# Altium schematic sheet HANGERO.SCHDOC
size A2
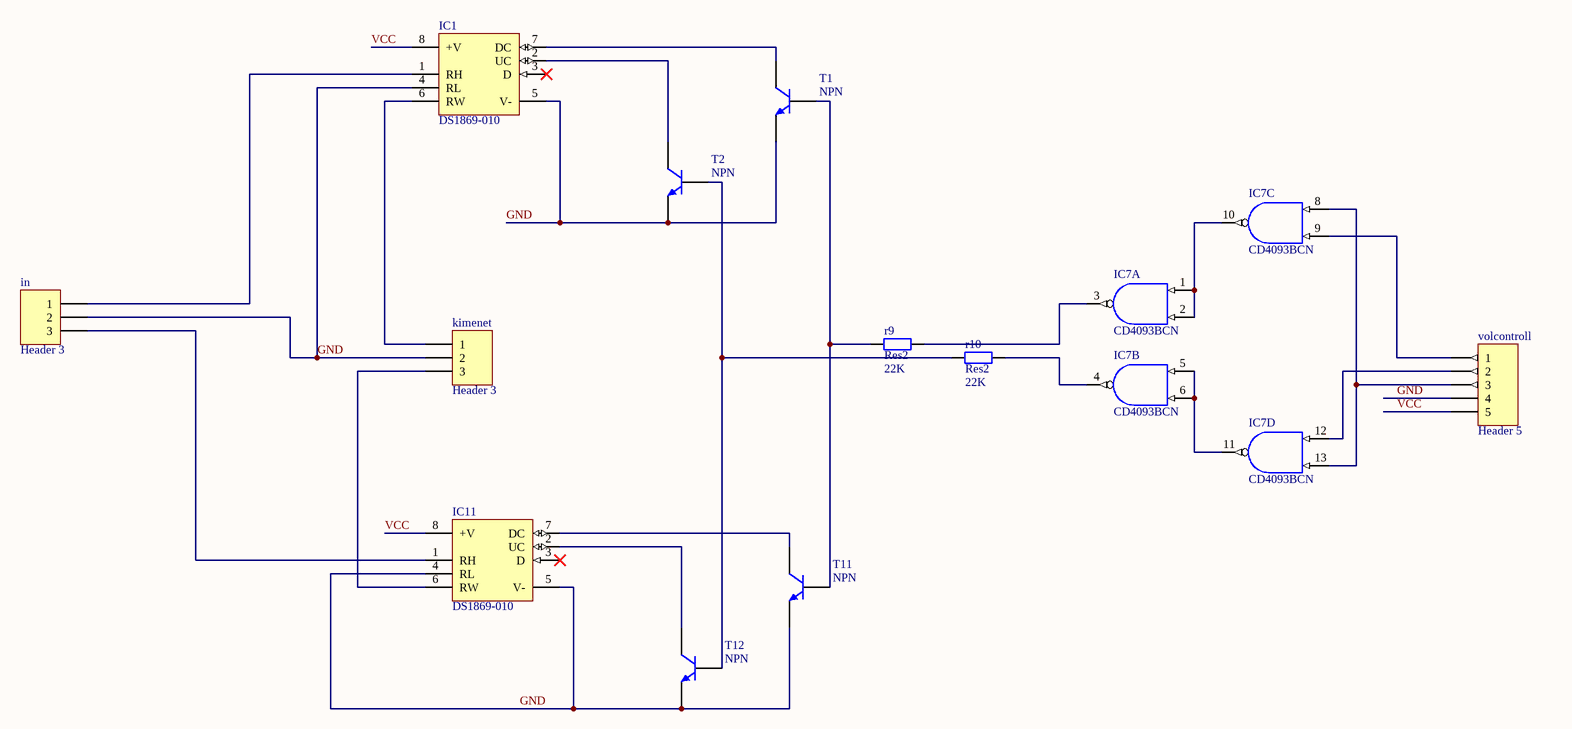
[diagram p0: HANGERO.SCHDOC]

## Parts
IC1  DS1869-010  [DIP8]
IC7  CD4093BCN  [N14A]  (parts A,B,C,D of 4)
IC11  DS1869-010  [DIP8]
in  Header 3  [HDR1X3]
kimenet  Header 3  [HDR1X3]
r9  Res2  value 22K  [AXIAL-0.4]
r10  Res2  value 22K  [AXIAL-0.4]
T1  NPN  [BCY-W3]
T2  NPN  [BCY-W3]
T11  NPN  [BCY-W3]
T12  NPN  [BCY-W3]
volcontroll  Header 5  [HDR1X5]

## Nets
GND: IC1.4(RL) IC1.5(V-) IC7.7(GND) IC11.4(RL) IC11.5(V-) in.2 kimenet.2 T1.3(E) T2.3(E) T11.3(E) T12.3(E) volcontroll.4
VCC: IC1.8(+V) IC7.14(VCC) IC11.8(+V) volcontroll.5
NetIC1_1: IC1.1(RH) in.1
NetIC1_2: IC1.2(UC) T2.1(C)
NetIC1_6: IC1.6(RW) kimenet.1
NetIC1_7: IC1.7(DC) T1.1(C)
NetIC7_1: IC7.1(A) IC7.2(B) IC7.10(L)
NetIC7_3: IC7.3(J) r9.2
NetIC7_4: IC7.4(K) r10.2
NetIC7_5: IC7.5(C) IC7.6(D) IC7.11(M)
NetIC7_8: IC7.8(E) IC7.13(H) volcontroll.3
NetIC7_9: IC7.9(F) volcontroll.1
NetIC7_12: IC7.12(G) volcontroll.2
NetIC11_1: IC11.1(RH) in.3
NetIC11_2: IC11.2(UC) T12.1(C)
NetIC11_6: IC11.6(RW) kimenet.3
NetIC11_7: IC11.7(DC) T11.1(C)
Netr9_1: r9.1 T1.2(B) T11.2(B)
Netr10_1: r10.1 T2.2(B) T12.2(B)

Not connected (* = marked no-connect by the designer): IC1 3(D)*; IC11 3(D)*

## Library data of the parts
IC1 IC11 = DS1869-010: 3V Dallastat Electronic Digital Rheostat; Package Information: Latest Revision: 1999
IC7 = CD4093BCN: Quad 2-Input NAND Schmitt Trigger; Package Information: Latest Revision: 2000
in kimenet = Header 3: Header, 3-Pin
r9 r10 = Res2: Resistor
T1 T2 T11 T12 = NPN: NPN Bipolar Transistor; Code - JEDEC: TO-226-AA
volcontroll = Header 5: Header, 5-Pin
